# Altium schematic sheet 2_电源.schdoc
size 431 x 309 mm; Symbol: Sheet-Symbol_A3; Device: Sheet-Symbol_A3; Company: 嘉立创EDA; Version: V1.0; Page Size: A3; @Project Name: 辉光管时钟成品; @Page Count: 2; @Update Date: 2024-03-15; @Create Date: 2024-01-25; @Schematic Name: 电源+控制部分; @Page No: 2; @Page Name: 电源
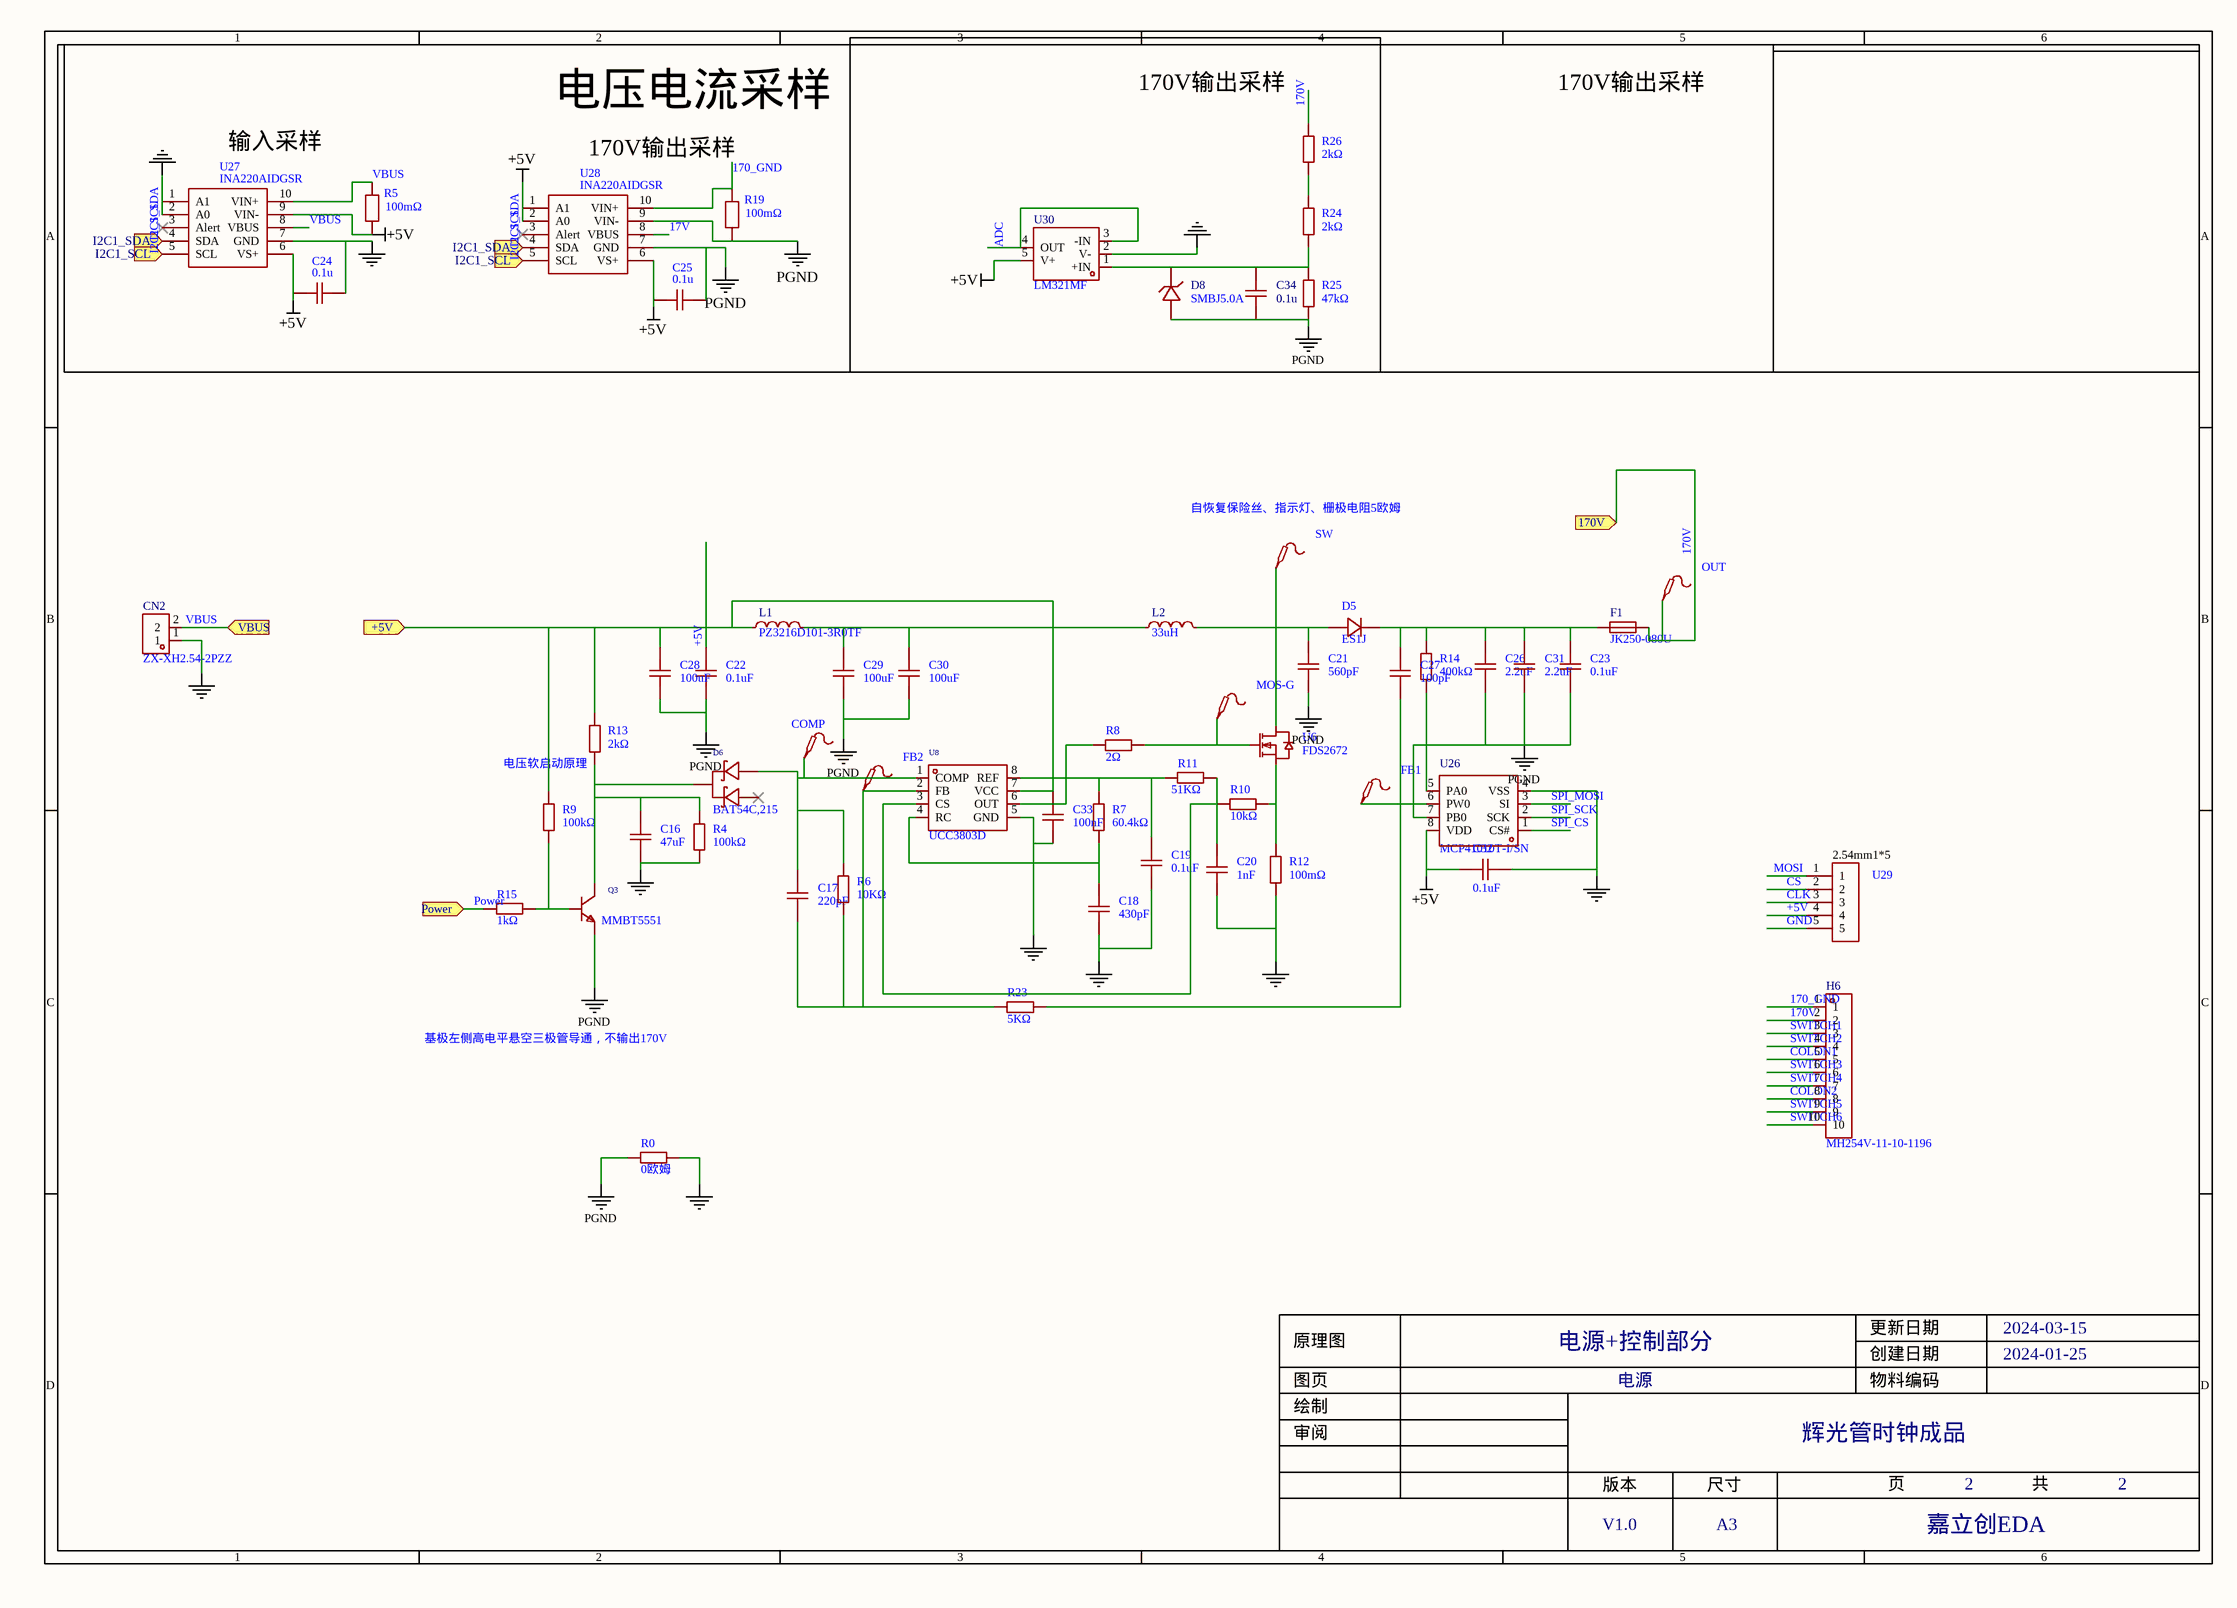
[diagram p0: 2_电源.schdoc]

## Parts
C16  47uF  [C0805]
C17  220pF  [c0603]
C18  430pF  [c0603]
C19  0.1uF  [c0603]
C20  1nF  [c0603]
C21  560pF  [c1206]
C22  0.1uF  [c0603]
C23  0.1uF  [c1206]
C24  0.1u  [C0603]
C25  0.1u  [C0603]
C26  2.2uF  [c1210]
C27  100pF  [C0805]
C28  100uF  [c1206]
C29  100uF  [c1206]
C30  100uF  [c1206]
C31  2.2uF  [c1210]
C32  0.1uF  [c0603]
C33  100nF  [C0603]
C34  0.1u  [C0603]
CN2  ZX-XH2.54-2PZZ  [CONN-TH_2P-P2.50_HX25003-2A]
COMP  (no value)  [Test-Point-0.5mm]
D5  ES1J  [sod-123_l2.7-w1.6-ls3.6-rd]
D6  BAT54C,215  [SOT-23-3_L2.9-W1.6-P1.90-LS2.8-BR]
D8  SMBJ5.0A  [SMB_L4.4-W3.6-LS5.3-RD]
F1  JK250-080U  [FUSE-TH_L5.8-W3.8-P5.10-D0.8]
FB1  (no value)  [Test-Point-0.5mm]
FB2  (no value)  [Test-Point-0.5mm]
H6  MH254V-11-10-1196  [HDR-TH_10P-P2.54-V-M]
L1  PZ3216D101-3R0TF  [l0603]
L2  33uH  [33uh功率电感]
MOS-G  (no value)  [Test-Point-0.5mm]
OUT  (no value)  [Test-Point-0.5mm]
Q3  MMBT5551  [SOT-23-3_L2.9-W1.3-P1.90-LS2.4-BR]
R0  0欧姆  [R0603]
R4  100kΩ  [r0603]
R5  100mΩ  [R0805]
R6  10KΩ  [r0603]
R7  60.4kΩ  [r0603]
R8  2Ω  [r0603]
R9  100kΩ  [r0603]
R10  10kΩ  [r0603]
R11  51KΩ  [r0603]
R12  100mΩ  [R0805]
R13  2kΩ  [r0603]
R14  400kΩ  [r0603]
R15  1kΩ  [r0603]
R19  100mΩ  [R0805]
R23  5KΩ  [r0603]
R24  2kΩ  [r0603]
R25  47kΩ  [r0603]
R26  2kΩ  [r0603]
SW  (no value)  [Test-Point-0.5mm]
U6  FDS2672  [SO-8_L4.9-W3.9-P1.27-LS6.0-BL]
U8  UCC3803D  [SOIC-8_L4.9-W3.9-P1.27-LS6.0-BL]
U26  MCP41010T-I/SN  [SOIC-8_L4.9-W3.9-P1.27-LS6.0-BL]
U27  INA220AIDGSR  [VSSOP-10_L3.0-W3.0-P0.50-LS4.9-BL]
U28  INA220AIDGSR  [VSSOP-10_L3.0-W3.0-P0.50-LS4.9-BL]
U29  (no value)  [2.54mm1*5]
U30  LM321MF  [SOT-23-5_L2.9-W1.6-P0.95-LS2.8-BL]

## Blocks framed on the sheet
电压电流采样: C24 C25 R5 R19 U27 U28
170V输出采样: C34 D8 R24-R26 U30

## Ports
170V (in), +5V (in), I2C1_SCL (in), I2C1_SDA (in), Power (in), VBUS (in)

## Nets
+5V: C22.2 C24.2 C25.2 C28.2 C32.2 C33.1 L1.1 R5.1 R9.2 R13.2 U8.7(VCC) U26.8(VDD) U27.6(VS+) U27.9(VIN-) U28.1(A1) U28.2(A0) U28.6(VS+) U29.4 U30.5(V+) ; port +5V
GND: C18.1 C19.1 C24.1 C32.1 C33.2 R0.2 U8.5(GND) U26.4(VSS) U27.1(A1) U27.2(A0) U27.7(GND) U29.5 U30.2(V-)
PGND: C16.1 C20.1 C21.1 C22.1 C23.1 C25.1 C26.1 C28.1 C29.1 C30.1 C31.1 C34.2 CN2.1 D8.2(A) Q3.2(E) R0.1 R4.1 R12.1 R19.1 R25.1 U26.7(PB0) U28.7(GND) U28.9(VIN-)
17V: U28.8(VBUS)
170_GND: H6.1 R19.2 U28.10(VIN+)
170V: F1.2 H6.2 OUT.1 R26.2 ; port 170V
ADC: U30.3(-IN) U30.4(OUT)
CLK: U29.3
COLON1: H6.5
COLON2: H6.8
CS: U29.2
I2C1_SCL: U27.5(SCL) U28.5(SCL) ; port I2C1_SCL
I2C1_SDA: U27.4(SDA) U28.4(SDA) ; port I2C1_SDA
MOSI: U29.1
Power: R15.2 ; port Power
SPI_CS: U26.1(CS#)
SPI_MOSI: U26.3(SI)
SPI_SCK: U26.2(SCK)
SWITCH1: H6.3
SWITCH2: H6.4
SWITCH3: H6.6
SWITCH4: H6.7
SWITCH5: H6.9
SWITCH6: H6.10
VBUS: CN2.2 R5.2 U27.8(VBUS) U27.10(VIN+) ; port VBUS
NetC16_2: C16.2 D6.3(K) Q3.3(C) R4.2 R13.1
NetC17_1: C17.1 FB2.1 R6.1 R23.2 U8.2(FB)
NetC17_2: C17.2 COMP.1 D6.1(A) R6.2 U8.1(COMP)
NetC18_2: C18.2 R7.1 U8.4(RC)
NetC19_2: C19.2 R7.2 R11.2 U8.8(REF)
NetC20_2: C20.2 R10.2 R11.1 U8.3(CS)
NetC21_2: C21.2 D5.2(A) L2.2 SW.1 U6.5(D) U6.6(D) U6.7(D) U6.8(D)
NetC23_2: C23.2 C26.2 C27.2 C31.2 D5.1(K) F1.1 R14.2
NetC27_1: C27.1 FB1.1 R23.1 U26.6(PW0)
NetC29_2: C29.2 C30.2 L1.2 L2.1
NetC34_1: C34.1 D8.1(C) R24.1 R25.2 U30.1(+IN)
NetMOS-G_1: MOS-G.1 R8.1 U6.4(G)
NetQ3_1: Q3.1(B) R9.1 R15.1
NetR8_2: R8.2 U8.6(OUT)
NetR10_1: R10.1 R12.2 U6.1(S) U6.2(S) U6.3(S)
NetR14_1: R14.1 U26.5(PA0)
NetR24_2: R24.2 R26.1

Not connected (* = marked no-connect by the designer): D6 2(A)*; U27 3(Alert)*; U28 3(Alert)*

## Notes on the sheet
- 170V输出采样
- (near U27) 输入采样
- (near SW) 自恢复保险丝、指示灯、栅极电阻5欧姆
- 电压软启动原理
- 基极左侧高电平悬空三极管导通，不输出170V

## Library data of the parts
C16-C23 C27-C30 C32 = CC0805KRX7R9BB104: Manufacturer: YAGEO(国巨); Symbol: capacitance; Add into BOM: yes; Tolerance: ±10%; Voltage Rated: 50V; Temperature Coefficient: X7R
C24 C25 C34 = 0.1u: Convert to PCB: yes
C26 C31 = CC0805KRX7R9BB104: Manufacturer: YAGEO(国巨); Symbol: capacitance; Add into BOM: yes; Tolerance: ±10%; Voltage Rated: 200V; Temperature Coefficient: X7R
C33 = CAP_0603: Symbol: CapAcitance; Convert to PCB: yes
CN2 = ZX-XH2.54-2PZZ: Manufacturer: Megastar(兆星); Add into BOM: yes; Pins Structure: 1x2P; Pitch: 2.54mm; Reference Series: XH; Number of PINs Per Row: 2; Current Rating (Max): 3A
COMP FB1 FB2 MOS-G OUT SW = Test-Point: Add into BOM: yes
D5 = ES1J_C691230: Manufacturer: DIODES(美台); Symbol: 1n4007_c9900004759; Add into BOM: yes
D6 = BAT54C,215: Manufacturer: Nexperia(安世); Add into BOM: yes; Diode Configuration: 1对共阴极; Reverse Voltage (Vr): 30V; Average Rectified Current (Io): 200mA; Forward Voltage (Vf@If): 800mV@100mA; Reverse Leakage Current (Ir): 2uA@25V
D8 = SMBJ5.0A_C726811: Manufacturer: TWGMC(台湾迪嘉); Add into BOM: yes
F1 = JK250-080U: Manufacturer: JK(金科); Symbol: JK250-080U_C369127; Add into BOM: yes; Operating Voltage (Max): 250V; Current Rating (Max): 3A; Hold Current: 80mA; Trip Current: 160mA; Maximum Time to Trip: 500ms
H6 = MH254V-11-10-1196: Manufacturer: XFCN(兴飞); Add into BOM: yes
L1 = PZ3216D101-3R0TF: Manufacturer: Sunlord(顺络); Symbol: sdfl1608s100ktf; Add into BOM: yes; Impedance @ Frequency: 100Ω@100MHz; Tolerance: ±25%; Current Rating: 3A; Circuits: 1; Value: 10uH
L2 = CXP0630-330M-AG(33uh): Manufacturer: DMBJ(振宝佳); Symbol: sdfl1608s100ktf; Add into BOM: yes; Type: 一体成型电感; Tolerance: ±20%; Rated Current: 2A; Saturation Current (Isat): 2.5A; DC Resistance (DCR): 240mΩ
Q3 = MMBT5551_C2145: Manufacturer: CJ(江苏长电/长晶); Symbol: bcx70ke6327htsa1; Add into BOM: yes; Transistor Type: NPN; Collector-Emitter Breakdown Voltage (Vceo): 160V; Collector Current (Ic): 600mA; Power Dissipation (Pd): 300mW; Collector Cut-Off Current (Icbo): 50nA; Collector-Emitter Saturation Voltage (VCE(sat)@Ic,Ib): 200mV@50mA,5mA; DC Current Gain (hFE@Ic,Vce): 200@10mA,5V; Transition Frequency (fT): 100MHz
R0 = Res_0603: Symbol: 电阻; Convert to PCB: yes
R4 R6-R11 R13-R15 R23-R26 = 0805W8F1002T5E_C17414: Manufacturer: UNI-ROYAL(厚声); Symbol: 电阻; Add into BOM: yes; Tolerance: ±1%; Power(Watts): 125mW; Temperature Coefficient: ±100ppm/℃; Overload Voltage (Max): 150V
R5 R19 = 5mΩ: Convert to PCB: yes; Origin Footprint: R1206
R12 = RL10FTNR160: Manufacturer: 大毅科技; Symbol: 电阻; Add into BOM: yes; Tolerance: ±1%; Power(Watts): 125mW; Temperature Coefficient: ±100ppm/℃; Overload Voltage (Max): 150V
U6 = FDS2672: Manufacturer: onsemi(安森美); Add into BOM: yes; Drain Source Voltage (Vdss): 200V; Continuous Drain Current (Id): 3.9A; Power Dissipation (Pd): 2.5W; Drain Source On Resistance (RDS(on)@Vgs,Id): 70mΩ@10V,3.9A; Gate Threshold Voltage (Vgs(th)@Id): 4V@250uA; Total Gate Charge (Qg@Vgs): 46nC@10V; Input Capacitance (Ciss@Vds): 2.535nF@100V
U8 = UCC3803D: Manufacturer: TI(德州仪器); Symbol: ucc3803dtrg4; Add into BOM: yes; Function: 升压型；降压型；升降压型; Number of Outputs: 1; Input Voltage: 3.6V~12V; Synchronous Rectification: 否; Topology: 反激式；降压式；正激式；升压式; Switching Frequency: 31kHz; Duty Cycle (Max): 99%
U26 = MCP41010T-I/SN: Manufacturer: MICROCHIP(美国微芯); Add into BOM: yes; Supply Voltage: 2.7V~5.5V; Resistance Value (Ohms): 10kΩ; Number of Taps: 256; Temperature Coefficient (Typ): 800ppm/℃; Precision: ±20%; Number of Channels: 1; Interface Type: SPI
U27 U28 = INA220AIDGSR: Manufacturer: TI(德州仪器); Symbol: INA220; Add into BOM: yes; Origin Footprint: MSOP-10_L3.0-W3.0-P0.50-LS5.0-BL
U29 = 2.54mm1*5: Add into BOM: yes
U30 = LM321MF: Manufacturer: UMW(友台半导体); Add into BOM: yes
